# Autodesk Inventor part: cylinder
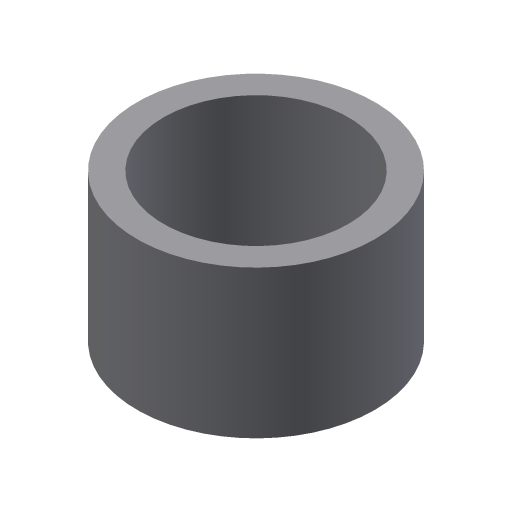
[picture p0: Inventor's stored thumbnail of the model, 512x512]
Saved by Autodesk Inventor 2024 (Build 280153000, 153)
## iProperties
Shininess: 64.0
Length Units: 11269
Angle Units: 11279
Time Units: 11290
Mass Units: 11283
Length Display Precision: 3
Angle Display Precision: 2
Compacted: True
Part Number: cylinder
Document SubType Name: Modeling
Created: 2003-01
Designer: Owner
Density: 1 g/cm^3
Material: Generic
Appearance: Default
Density: 0.0
Volumn: 0.0
Area: 0.0
PropertySet Name: Model Information
Control State: 0
Master: False
Checked Out: False
Author: Owner
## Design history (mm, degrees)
sketch "Sketch1"
  geometry: C1 r 112.5 at (0, 0); C2 r 87.5 at (0, 0)
  constraints: 2 centre point, 1 coincident, 1 concentric
  dimensions: "d0" = 225 diameter of C1; "d1" = 175 diameter of C2
extrude "Extrusion1" new body sketch "Sketch1" stored distance "d2" = 140; taper "d3" = 0 deg
body "Solid1"
